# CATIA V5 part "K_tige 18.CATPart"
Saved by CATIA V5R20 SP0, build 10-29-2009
Part number: tige 18
Publications: "longueur tige", "demi largeur tige", "demi largeur balancier", "epaisseur pieces", "Plan.-55", "liaison 3/18 sur 18", "Droite.1"
Bounding box of the stored display mesh (mm): x -72.5 to 0, y -600.025 to -67.527, z -17.473 to 226.143
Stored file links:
  G:\Khaled_CFAO_2011\SIL\SIL_GR2\mdardier\Khaled\CAD_ThinkMOTION\K_tige 18.CATPart
  G:\Khaled_CFAO_2011\SIL\SIL_GR2\mdardier\Khaled\CAD_ThinkMOTION\K_ass_tandem.CATProduct
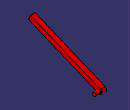
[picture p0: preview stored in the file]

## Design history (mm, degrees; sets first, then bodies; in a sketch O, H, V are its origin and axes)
External parameters (linked from other documents)
  `External.longueur tige` = 550 mm
  `External.demi largeur tige` = 17.5 mm
  `External.demi largeur balancier` = 50 mm
  `External.epaisseur pieces` = 30 mm
Set1
  Plane1 "Plan.-55": linked copy from another document
  Point1 "liaison 3/18 sur 18": linked copy from another document
  Line1: linked copy from another document
Body1 (main body)
  Sketch1 on Plane1, origin (-55, 0, 0), H (0, 1, 0), V (0, 0, 1)
    construction line L1 (-593.3438, 209.9681) -> (-85, 0)
    point P2 (-85, 0)
    line L2 (-586.663, 226.1427) -> (-78.3192, 16.1746)
    line L3 (-91.6808, -16.1746) -> (-600.0246, 193.7935)
    arc A1 centre (-85, 0) radius 17.5 from (-78.3192, 16.1746) to (-91.6808, -16.1746) cw
    point P3 (-586.663, 226.1427)
    reference projected point E1 (-85, 0) from Point1
    reference projected line E2 (-593.3438, 209.9681) -> (-85, 0) from Line1
    line L4 (-586.663, 226.1427) -> (-600.0246, 193.7935)
    point P7 (-586.663, 226.1427)
    distance L1 L2 = 17.5 {= `External.demi largeur tige`}
    length L2 = 550 {= `External.longueur tige`}
    tangency: A1 L2, A1 L3
    coincidence: P2 E1, P7 L2, P7 P3
    parallelism: L1 E2
    perpendicularity: L4 L1, L4 L3
  Pad1: profile Sketch1, direction (1, 0, 0), length 17.5 {= `External.demi largeur tige`}, mirrored extent
  Sketch2 on end face of Pad1, origin (-37.5, 0, 0), H (0, 1, 0), V (0, 0, 1)
    circle A1 centre (-85, 0) radius 12.5
    point P1 (-85, 0)
    reference projected point E1 (-85, 0) from Point1
    radius A1 = 12.5 {= `External.demi largeur balancier` /4}
    coincidence: P1 E1
  Pad2: profile Sketch2, direction (1, 0, 0), length 37.5 {= `External.demi largeur balancier` /2-`External.demi largeur tige` +`External.epaisseur pieces`}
